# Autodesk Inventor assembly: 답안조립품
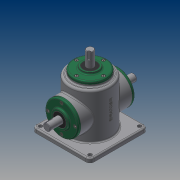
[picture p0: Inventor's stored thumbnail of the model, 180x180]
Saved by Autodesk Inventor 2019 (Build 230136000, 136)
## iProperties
Created: 2019-03
Part Number: 답안조립품
Material: 일반
Document SubType Name: Assembly
Designer: PC312-17
Author: PC312-17
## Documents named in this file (16)
- C:\Users\PC312-17\Desktop\490314V1007\답안조립품.iam
- C:\Users\PC312-17\Desktop\490314V1007\본체.ipt
- C:\Users\PC312-17\Desktop\490314V1007\커버.ipt
- C:\Users\PC312-17\Desktop\490314V1007\볼트 M4.ipt
- 볼트 M4.ipt
- C:\Users\PC312-17\Desktop\490314V1007\오일 실.ipt
- 오일 실.ipt
- C:\Users\PC312-17\Desktop\490314V1007\베어링 6203.ipt
- C:\Users\PC312-17\Desktop\490314V1007\메인 축.ipt
- 메인 축.ipt
- C:\Users\PC312-17\Desktop\490314V1007\서브 축.ipt
- 서브 축.ipt
- C:\Users\PC312-17\Desktop\490314V1007\키 5x5.ipt
- C:\Users\PC312-17\Desktop\490314V1007\키 4x4.ipt
- C:\Users\PC312-17\Desktop\490314V1007\메인 베벨기어.ipt
- C:\Users\PC312-17\Desktop\490314V1007\서브 베벨기어.ipt
